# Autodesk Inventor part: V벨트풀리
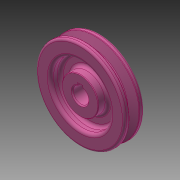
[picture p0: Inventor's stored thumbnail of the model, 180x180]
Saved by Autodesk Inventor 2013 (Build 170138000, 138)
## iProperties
Created: 2018-11
Part Number: V벨트풀리
Material: 알루미늄 6061
Document SubType Name: Modeling
Designer: mduedu
Density: 1 g/cm^3
Author: mduedu
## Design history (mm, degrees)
sketch "스케치1"
  geometry: L1 (-9.5, 0)-(9.5, 0); L2 (9.5, 0)-(9.5, 42.7); L3 (9.5, 42.7)-(4.877, 42.7); L4 (-9.5, 42.7)-(-9.5, 0); L5 (-4.877, 42.7)-(-1.953, 33.7); L6 (-1.953, 33.7)-(1.953, 33.7); L7 (1.953, 33.7)-(4.877, 42.7); L8 (0, 0)-(0, 42.7); L9 (-9.5, 40)-(9.5, 40); L10 (-4.877, 42.7)-(-9.5, 42.7); L11 (4.877, 42.7)-(-4.877, 42.7); 3 further points
  constraints: 22 end point, 6 point on line, 4 parallel, 3 perpendicular, 2 midpoint, 1 coincident, 1 horizontal, 1 vertical, 1 other
  dimensions: "d2" = 19 distance of L2.end L4.start; "d3" = 80 diameter of L9 L1; "d4" = 36 deg angle of L7 L5; "d5" = 6.3 distance between parallel lines of L6 L9; "d6" = 8 distance of point (4, 40) point (-4, 40); "d27" = 2.7 distance between parallel lines of L3 L9
revolve "회전1" sketch "스케치1" stored, may be unused: angle "d7" = 90 deg
sketch "스케치2"
  geometry: L1 (-2.5, 7.071)-(2.5, 7.071); L2 (2.5, 7.071)-(2.5, 9.8); L3 (2.5, 9.8)-(-2.5, 9.8); L4 (-2.5, 9.8)-(-2.5, 7.071); A1 r 7.5 centre (0, 0) between (-2.5, 7.071) and (2.5, 7.071); 1 further point
  constraints: 8 end point, 2 parallel, 2 point on circle, 1 centre point, 1 coincident, 1 horizontal, 1 perpendicular
  dimensions: "d8" = 15 diameter of A1; "d10" = 17.3 dimension on A1 L3; "d11" = 5 distance of L2.end L3.end
extrude "돌출1" cut sketch "스케치2" stored distance "d12" = 10; taper "d13" = 0 deg
chamfer "모따기1" distance "d14" = 1; stored, may be unused: second distance "d15" = 2, angle "d16" = 45 deg
fillet "모깎기1" dims "d17" = 1, "d18" = 0.5, "d19" = 2
sketch "스케치3"
  geometry: C1 r 17.5 at (0, 0); C2 r 28.5 at (0, 0); 1 further point
  constraints: 2 centre point, 2 coincident
  dimensions: "d20" = 35 diameter of C1; "d23" = 57 diameter of C2
extrude "돌출2" cut sketch "스케치3" distance "d24" = 9.5; taper "d25" = 0 deg
fillet "모깎기2" dims "d26" = 3
chamfer "모따기2" distance "d28" = 0.5; stored, may be unused: second distance "d29" = 2, angle "d30" = 45 deg
node "솔리드1"
